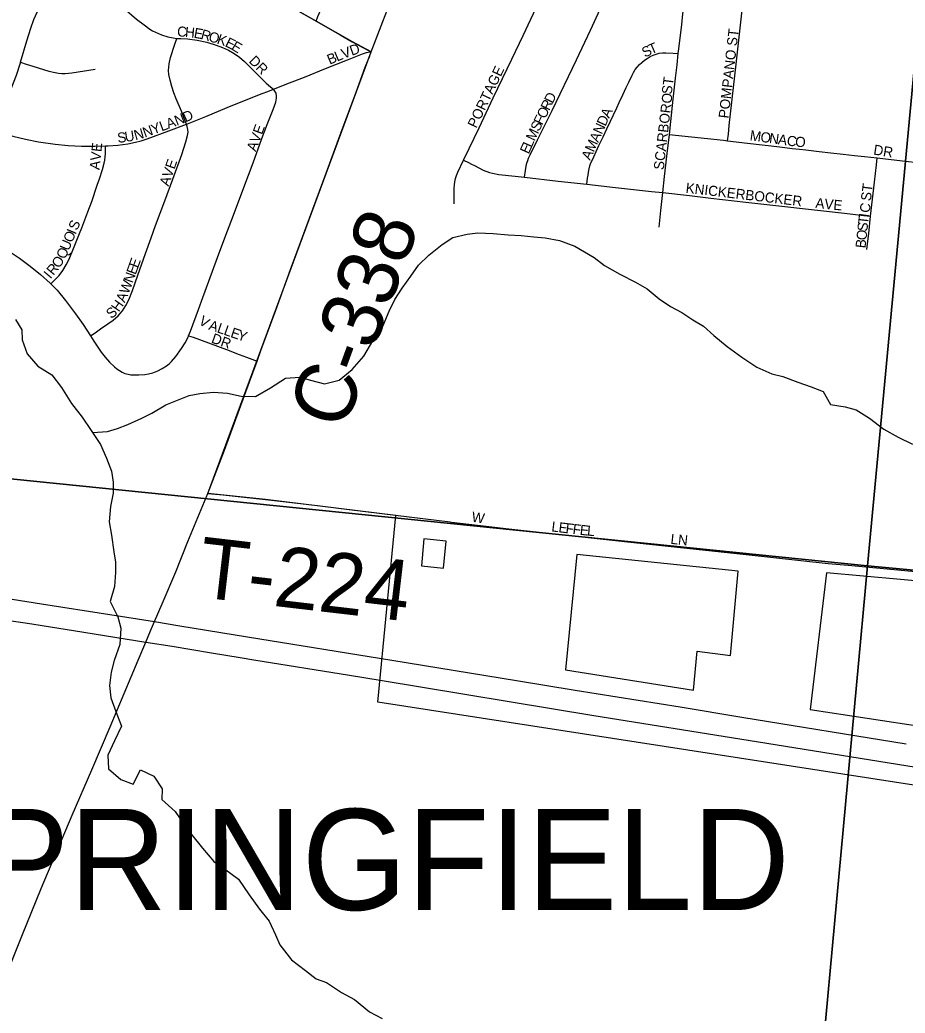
# Model space of a CAD drawing. Extents: x 1410790 to 1770854, y 566777 to 831614.
# Drawn here: x 1593644 to 1598025, y 690858 to 695774 of the extents above; entities that cross this region are included whole.
import ezdxf

# ---------------------------------------------------------------- set-up
doc = ezdxf.new("R2010")
doc.units = 0
for name, color, linetype in [('GM_X_City_Street', 7, 'Continuous'), ('GM_X_City_Street_Text', 7, 'Continuous'), ('GM_X_Corporation', 7, 'Continuous'), ('GM_X_Corporation_Text', 7, 'Continuous'), ('GM_X_County_Road', 7, 'Continuous'), ('GM_X_County_Road_Text', 7, 'Continuous'), ('GM_X_Interstate_Route', 7, 'Continuous'), ('GM_X_Minor_River', 7, 'Continuous'), ('GM_X_Section', 7, 'Continuous'), ('GM_X_Township_Road', 7, 'Continuous'), ('GM_X_Township_Road_Text', 7, 'Continuous'), ('GM_X_Township_Subdivision', 7, 'Continuous'), ('GM_X_Township_Subdivision_Text', 7, 'Continuous')]:
    doc.layers.add(name, color=color, linetype=linetype)

msp = doc.modelspace()

# ---------------------------------------------------------------- linework, layer by layer
at = {"layer": 'GM_X_City_Street'}
for points in [[(1595110.1, 695768.1), (1595119.1, 695790.4), (1595131.2, 695820.8), (1595178.5, 695942.9), (1595289.8, 696233.3), (1595315.8, 696299.8)], [(1595382.9, 695615.7), (1595440.5, 695766.1), (1595463.1, 695825), (1595487.8, 695889.4), (1595511.8, 695951.8), (1595534.4, 696010.7), (1595581.9, 696134.9), (1595587.8, 696150.3)], [(1595839.7, 695079.8), (1595867, 695137.8), (1595917.1, 695240.6), (1595985.7, 695388.6), (1596079, 695579.3), (1596134.3, 695696.7), (1596210.5, 695859), (1596315.6, 696080.8), (1596330.3, 696111)], [(1596141.3, 694995.2), (1596146.7, 695028.5), (1596151.8, 695059.3), (1596154.5, 695069.2), (1596157.5, 695078.2), (1596161.6, 695088.9), (1596169.7, 695106.9), (1596204.9, 695180.4), (1596277.9, 695326.3), (1596397.9, 695576.2), (1596468, 695723.4), (1596516.6, 695826.8), (1596588.4, 695979.6), (1596603.6, 696011.8)], [(1596902.6, 695607.3), (1596903.8, 695618.7), (1596909.9, 695669.7), (1596919.6, 695751.9), (1596925.7, 695803.7), (1596939.1, 695916), (1596942.6, 695945.7)], [(1597146.7, 695175.8), (1597150.3, 695208.8), (1597155, 695251.1), (1597188.7, 695554.2), (1597217.7, 695807.8), (1597226.5, 695885.8), (1597229.6, 695913.8)], [(1595367.5, 695576.3), (1595373.4, 695590.8), (1595378.1, 695603.2), (1595382.9, 695615.7)], [(1596449.7, 694960.7), (1596453.9, 694990.3), (1596456, 695005.1), (1596458, 695021.1), (1596461, 695036.9), (1596465.3, 695052.4), (1596469.8, 695066), (1596477.1, 695081.7), (1596503, 695138.2), (1596509.9, 695151.7), (1596530.9, 695195.3), (1596549.5, 695235.1), (1596567.1, 695272.7), (1596581.5, 695303.4), (1596597.8, 695338.1), (1596610.2, 695364.7), (1596628.4, 695403.5), (1596645.2, 695439.4), (1596657.4, 695465.4), (1596673.6, 695500), (1596680.7, 695514.3), (1596689.3, 695528), (1596699.4, 695540.8), (1596710.6, 695552.7), (1596722.6, 695563.9), (1596735.2, 695574.2), (1596748.5, 695583.7), (1596762.6, 695592.1), (1596777.4, 695599.1), (1596792.7, 695604.7), (1596808.6, 695608.7), (1596824.7, 695610.8), (1596841.1, 695611), (1596876.7, 695608.8), (1596902.6, 695607.3)], [(1596858.6, 695207.4), (1596865.8, 695271.8), (1596877.8, 695381.3), (1596889.2, 695484.9), (1596896.4, 695550.9), (1596902.6, 695607.3)], [(1596826.4, 694919), (1596835, 694998.2), (1596847.9, 695112.8), (1596858.6, 695207.4)], [(1596858.6, 695207.4), (1596889.5, 695204.1), (1597126.5, 695178.2), (1597146.7, 695175.8)], [(1597146.7, 695175.8), (1597244.9, 695164.1), (1597404.7, 695145.2), (1597465.7, 695138.3), (1597501.9, 695134.2), (1597534.5, 695130.5), (1597600, 695123.2), (1597657.2, 695116.7), (1597718.7, 695109.8), (1597775.2, 695103.4), (1597824.8, 695097.8), (1597887.7, 695090.9)], [(1595793.2, 694863), (1595793.2, 694895.4), (1595793.2, 694910.6), (1595792.9, 694925.7), (1595793.3, 694941), (1595794.4, 694956.9), (1595796.7, 694973.1), (1595800.4, 694989), (1595805.2, 695004.5), (1595811, 695019.8), (1595839.7, 695079.8)], [(1595839.7, 695079.8), (1595864.4, 695067.4), (1595878.7, 695060.3), (1595893, 695052.7), (1595936.9, 695030.9), (1595967.3, 695019.1), (1595983, 695014.7), (1596014.9, 695008.5), (1596095.9, 695000.4), (1596141.3, 694995.2)], [(1597854.7, 694802), (1597873.9, 694970.1), (1597883.7, 695055.9), (1597887.7, 695090.9)], [(1597887.7, 695090.9), (1598012.9, 695077.2), (1598102.8, 695067.3), (1598160.7, 695061), (1598188.8, 695057.9)], [(1596141.3, 694995.2), (1596307.8, 694976.6), (1596449.7, 694960.7)], [(1596449.7, 694960.7), (1596591.5, 694945), (1596770.7, 694925.1), (1596826.4, 694919)], [(1596808, 694748.2), (1596816.8, 694830.3), (1596826.4, 694919)], [(1596826.4, 694919), (1596958.3, 694904.3), (1597063.7, 694892.3), (1597237.5, 694872.5), (1597724.5, 694817), (1597820.4, 694805.9), (1597854.7, 694802)], [(1597835.6, 694637.4), (1597840.7, 694679.5), (1597845, 694717.1), (1597854.7, 694802)], [(1595780.3, 693288.6), (1595952.1, 693267.6), (1596049.7, 693256.7), (1596228.7, 693236.5), (1596456.6, 693212.3), (1596635.5, 693193), (1596944.7, 693159), (1597237.8, 693127.4), (1597644.9, 693084.2), (1597742.7, 693075.7), (1597970.9, 693054), (1598215.3, 693030.4), (1598464.3, 693001.6), (1598550.5, 692991.9), (1598670.4, 692978.3)]]:
    msp.add_lwpolyline(points, dxfattribs=at)
at = {"layer": 'GM_X_Corporation'}
msp.add_lwpolyline([(1598367.8, 691940.9), (1595414.7, 692397), (1595503.8, 693321.5), (1594859, 693400.6), (1594573.1, 693429.9), (1595382.9, 695615.7), (1595289.7, 695665.1), (1595110.1, 695768.1), (1594846.9, 695917.7)], dxfattribs=at)
for points in [[(1595753.4, 693194.7), (1595643.8, 693206.1), (1595631.3, 693071.7), (1595740.7, 693060.3)], [(1596399.9, 693127.7), (1596345, 692557.5), (1596977.3, 692456.4), (1596996.3, 692648.7), (1597161.2, 692628.6), (1597199.7, 693044.7)], [(1597636.9, 693037.6), (1597555.3, 692360.6), (1598119.6, 692275.5), (1598185.5, 692987.3)]]:
    msp.add_lwpolyline(points, close=True, dxfattribs=at)
at = {"layer": 'GM_X_County_Road'}
for points in [[(1594817.7, 694084.4), (1594836.8, 694137.1), (1594910.4, 694337.5), (1594983.2, 694538.3), (1595160.1, 695015.7), (1595238.9, 695231.7), (1595307.5, 695416.5), (1595352.8, 695539.9), (1595367.5, 695576.3)], [(1594573.1, 693429.9), (1594614.4, 693536.5), (1594655.6, 693643.7), (1594780.7, 693982.7), (1594817.7, 694084.4)], [(1594090.4, 692275.7), (1594229.6, 692605.1), (1594266.4, 692694.8), (1594289.5, 692750.9), (1594309.1, 692795.8), (1594347.7, 692883.8), (1594415.4, 693041.7), (1594475.3, 693191.9), (1594573.1, 693429.9)], [(1593504.9, 690861.3), (1593535.9, 690942.2), (1593614.2, 691140.3), (1593656.5, 691247), (1593749.7, 691474.5), (1593902.4, 691837), (1594000.3, 692062.5), (1594090.4, 692275.7)]]:
    msp.add_lwpolyline(points, dxfattribs=at)
at = {"layer": 'GM_X_Interstate_Route'}
for points in [[(1591241, 693062.9), (1591426.3, 693049.1), (1591646.2, 693033.2), (1592077.4, 692990.9), (1592343.8, 692964.5), (1592685.2, 692925.4), (1593005.4, 692884.2), (1593329.9, 692839.8), (1593702, 692784.8), (1593960.9, 692743.6), (1594266.4, 692694.8), (1594397.4, 692673.8), (1594592.6, 692641.4)], [(1593426.7, 692934.5), (1593750.7, 692884.2), (1594088.9, 692831.3), (1594309.1, 692795.8), (1594435.7, 692775.3), (1594770.6, 692720.3), (1595484.5, 692604.7), (1596101.1, 692504.7), (1596392.8, 692456.9), (1596911.3, 692373.5), (1597216.8, 692323), (1598030.7, 692191)], [(1594592.6, 692641.4), (1594734.6, 692617.8), (1594801, 692607.2)], [(1594801, 692607.2), (1595275.7, 692531.2), (1595426.6, 692506.2)], [(1595426.6, 692506.2), (1596485.1, 692331.4), (1597248, 692209.8), (1598356.7, 692030.2), (1598819.7, 691955.1), (1599147.3, 691901.2), (1599856.9, 691786.1)]]:
    msp.add_lwpolyline(points, dxfattribs=at)
at = {"layer": 'GM_X_Minor_River'}
for points in [[(1594003.3, 693731.9), (1594077, 693736.5), (1594127, 693752.2), (1594177.1, 693771.8), (1594247.3, 693803.3), (1594297.4, 693827), (1594365.6, 693868.5), (1594415.7, 693888.2), (1594481.8, 693915.7), (1594533.8, 693925.3), (1594601.8, 693930.8), (1594671.6, 693926.3), (1594739.4, 693911.8), (1594809.3, 693909.2), (1594883.6, 693952.7), (1594957.8, 694000.2), (1595029.8, 694005.7), (1595081.6, 693991.3), (1595151.4, 693972.8), (1595223.4, 693990.2), (1595287.7, 694043.8), (1595346.1, 694109.4), (1595390.6, 694185.2), (1595441.1, 694260.8), (1595471.6, 694332.7), (1595500, 694390.5), (1595536.4, 694446.3), (1595578.8, 694506), (1595617.1, 694559.8), (1595667.4, 694609.5), (1595733.8, 694663), (1595785.9, 694696.7), (1595858, 694714.1), (1595910, 694719.7), (1595985.8, 694717.2), (1596059.7, 694710.6), (1596125.6, 694706.1), (1596187.4, 694699.6), (1596243.3, 694695.2), (1596315.1, 694682.7), (1596390.8, 694654.1), (1596486.3, 694597.3), (1596537.9, 694558.9), (1596613.5, 694516.2), (1596691.1, 694475.6), (1596748.8, 694443.2), (1596808.3, 694392.7), (1596864, 694356.2), (1596919.7, 694325.8), (1596975.3, 694289.3), (1597027, 694258.9), (1597078.6, 694212.4), (1597144.1, 694157.9), (1597217.6, 694105.3), (1597291.1, 694054.7), (1597364.8, 694022.1), (1597420.6, 694009.6), (1597494.3, 693981), (1597560.1, 693958.5), (1597619.8, 693934), (1597655.3, 693869.7), (1597729.1, 693859.1), (1597782.9, 693844.7), (1597848.5, 693802.2), (1597920, 693747.6), (1597991.6, 693709), (1598061.3, 693674.4)], [(1593621.7, 694290.4), (1593653.3, 694240.1), (1593654.9, 694190.1), (1593680.4, 694121.8), (1593731.9, 694059.4), (1593801.5, 694016.8), (1593848.9, 693954.4), (1593898.3, 693876), (1593951.7, 693807.5), (1593997.1, 693741.1), (1594042.6, 693672.7), (1594072, 693604.4), (1594097.5, 693540.2), (1594105.1, 693486.1), (1594104.7, 693432), (1594092.2, 693366.1), (1594085.6, 693290.1), (1594097.1, 693223.9), (1594108.5, 693141.8), (1594116.1, 693089.7), (1594117.7, 693039.6), (1594111.2, 692969.6), (1594090.7, 692895.7), (1594128.1, 692819.3), (1594143.6, 692763.2), (1594139, 692683.1), (1594110.5, 692603.3), (1594096, 692545.3), (1594087.6, 692479.3), (1594093.1, 692419.2)], [(1594093.1, 692419.2), (1594118.6, 692351), (1594146, 692278.7), (1594111.5, 692204.9), (1594079, 692135.1), (1594082.5, 692067), (1594144, 692014.5), (1594203.7, 691992), (1594240.2, 692061.8), (1594305.9, 692031.3), (1594347.4, 691968.9), (1594347, 691914.9), (1594412.5, 691856.3), (1594452, 691798), (1594493.5, 691741.6), (1594546.9, 691675.2), (1594604.3, 691608.7), (1594656, 691572.3), (1594725.5, 691521.7), (1594778.9, 691443.2), (1594830.3, 691372.8), (1594877.8, 691312.4), (1594909.2, 691246.1), (1594930.8, 691195.9), (1594988.2, 691121.4), (1595057.7, 691068.8), (1595109.3, 691028.4), (1595161.1, 691010), (1595234.7, 690959.4), (1595300.3, 690924.9), (1595373.8, 690864.3), (1595437.4, 690831.8)]]:
    msp.add_lwpolyline(points, dxfattribs=at)
at = {"layer": 'GM_X_Section'}
for points in [[(1593108.3, 699057.6), (1598351.3, 698519.7), (1597838.4, 693072.3), (1592523.5, 693611.4)], [(1598351.3, 698519.7), (1603688.3, 697982.3), (1603189.9, 692572.7), (1597838.4, 693072.3)], [(1592523.5, 693611.4), (1597838.4, 693072.3), (1597349.3, 687756.6), (1592038.7, 688317.6)], [(1597838.4, 693072.3), (1603189.9, 692572.7), (1602694.7, 687247), (1597349.3, 687756.6)]]:
    msp.add_lwpolyline(points, close=True, dxfattribs=at)
at = {"layer": 'GM_X_Township_Road'}
msp.add_lwpolyline([(1594573.1, 693429.9), (1594650.4, 693423.5), (1594709.5, 693416.9), (1594859, 693400.6), (1594946, 693390.9), (1595116.4, 693370), (1595273.4, 693350.7), (1595435.3, 693330.9), (1595773.4, 693289.4), (1595780.3, 693288.6)], dxfattribs=at)
at = {"layer": 'GM_X_Township_Subdivision'}
for points in [[(1593646.8, 695564), (1593678, 695670), (1593698.5, 695732.5), (1593713.1, 695776.8), (1593720.4, 695794.2), (1593727.3, 695809.1), (1593735.5, 695823.3), (1593745, 695836.8), (1593755.8, 695849.2), (1593767.6, 695860.6), (1593780.2, 695871), (1593793.7, 695880.4), (1593807.9, 695888.7), (1593822.7, 695895.9), (1593838, 695901.9), (1593853.7, 695906.7), (1593869.8, 695910.2), (1593902.4, 695914), (1593935.2, 695916.8), (1593984.3, 695921.1), (1594016.9, 695925.3), (1594033, 695928.4), (1594048.9, 695932.6), (1594064.4, 695939.4)], [(1594064.4, 695939.4), (1594075, 695919.1), (1594087.2, 695900.1), (1594098.2, 695887.1), (1594111.1, 695873.4), (1594172.6, 695819.2), (1594196.2, 695799.1), (1594221.3, 695778.4), (1594258.4, 695749.1), (1594286.6, 695728.3), (1594300.5, 695719.8), (1594315, 695712.5), (1594345.3, 695700.6), (1594376.4, 695690.8), (1594402.2, 695684.7), (1594420.9, 695682.2)], [(1594846.9, 695917.7), (1594876.4, 695901.2), (1595075.2, 695788.2), (1595110.1, 695768.1)], [(1595110.1, 695768.1), (1595228.5, 695700), (1595287.6, 695666.2), (1595368.9, 695623.1), (1595382.9, 695615.7)], [(1594467.9, 695258.1), (1594460.8, 695278.4), (1594448.5, 695307.9), (1594442.9, 695323.1), (1594417.4, 695382.6), (1594405.6, 695412.9), (1594395.4, 695443.9), (1594386.9, 695475.5), (1594381.2, 695503.3), (1594380, 695524.1), (1594380.2, 695539.8), (1594382.6, 695556), (1594389.5, 695587.8), (1594393.6, 695603.4), (1594403.4, 695633.7), (1594409, 695649), (1594420.9, 695682.2)], [(1594420.9, 695682.2), (1594424.2, 695681.7), (1594440.2, 695681.4), (1594472.6, 695679.7), (1594520.9, 695673.4), (1594568.6, 695663), (1594615.5, 695649.3), (1594646.1, 695637.9), (1594675.6, 695624.4), (1594703.6, 695607.9), (1594730, 695588.8), (1594754.9, 695567.8), (1594778.6, 695545.4), (1594836.8, 695487.4), (1594862.8, 695461.4), (1594884, 695442.8), (1594898.4, 695431)], [(1594898.4, 695431), (1594978.8, 695462.5), (1595052.1, 695491.2), (1595156.9, 695533.3), (1595265.4, 695577), (1595339.5, 695605.8), (1595348.9, 695609.1), (1595359.6, 695612.2), (1595367.6, 695613.7), (1595382.9, 695615.7)], [(1593495.1, 695230.3), (1593514.9, 695262.9), (1593554.7, 695335), (1593576.8, 695379), (1593596.8, 695424), (1593626.2, 695500.2), (1593646, 695561.2), (1593646.8, 695564)], [(1593646.8, 695564), (1593674, 695555.4), (1593707.3, 695544.9), (1593786.7, 695520.9), (1593819, 695513.2), (1593835.3, 695510.6), (1593851.8, 695509.1), (1593868.3, 695509), (1593901.3, 695512.5), (1594016, 695530.5)], [(1594467.9, 695258.1), (1594472.6, 695259.9), (1594563.5, 695296.4), (1594669.2, 695340.2), (1594714.1, 695358.3), (1594842.3, 695409.6), (1594871.2, 695420.3), (1594898.4, 695431)], [(1594478.9, 694210.9), (1594488.6, 694233.7), (1594527.1, 694341.4), (1594549.6, 694399.6), (1594633.9, 694629.9), (1594672, 694730.7), (1594700.8, 694806.9), (1594752.3, 694944), (1594797.8, 695066), (1594841.1, 695186.9), (1594867.9, 695256.4), (1594897.2, 695330), (1594910.5, 695367.6), (1594914, 695386), (1594914, 695396.7), (1594911.4, 695411.9), (1594906.2, 695421.4), (1594898.4, 695431)], [(1593993.2, 694209.8), (1594016.3, 694225.9), (1594042.8, 694244.3), (1594079, 694269.4), (1594104.8, 694287.3), (1594129.5, 694308.6), (1594140.7, 694320.5), (1594151, 694333.2), (1594160.4, 694346.6), (1594168.7, 694360.6), (1594182.3, 694389.1), (1594200.6, 694434.1), (1594227.5, 694511), (1594265.4, 694618.6), (1594293, 694695.3), (1594315.5, 694756.5), (1594360.6, 694878.7), (1594400, 694985.8), (1594444.4, 695108.5), (1594465.2, 695170.3), (1594473.6, 695201.8), (1594475.9, 695217.9), (1594475.1, 695231), (1594472, 695246.3), (1594467.9, 695258.1)], [(1594067.8, 695150.6), (1594080, 695151), (1594129.1, 695154.8), (1594177.9, 695161.2), (1594215.1, 695168.2), (1594243.8, 695175.1), (1594273.3, 695184.7), (1594380.5, 695225.4), (1594467.9, 695258.1)], [(1593495.1, 695230.3), (1593545, 695216), (1593608, 695198.1), (1593672, 695183.2), (1593736.5, 695171), (1593817.8, 695159.6), (1593883.1, 695153.1), (1593948.7, 695149.4), (1594014.4, 695148.8), (1594067.8, 695150.6)], [(1593797.3, 694467.6), (1593819.4, 694490), (1593837.5, 694508.4), (1593856, 694533.4), (1593872.8, 694561.3), (1593887.4, 694590.4), (1593913, 694650.3), (1593939, 694716.8), (1593949.8, 694745.6), (1593979.9, 694824.4), (1593999.1, 694874.9), (1594026.8, 694955.7), (1594037, 694986.7), (1594052.8, 695032.9), (1594061.4, 695064.2), (1594064.5, 695080), (1594066.2, 695096), (1594066.7, 695111.1), (1594067.8, 695150.6)], [(1593162, 694877.1), (1593206.6, 694850.3), (1593262.7, 694818.3), (1593490.2, 694691), (1593587.6, 694631), (1593641.9, 694594.6), (1593694.4, 694555.7), (1593745.2, 694514.5), (1593794, 694471), (1593797.3, 694467.6)], [(1593797.3, 694467.6), (1593811.6, 694452.7), (1593827.8, 694435.6), (1593868.9, 694384.7), (1593918.4, 694319.7), (1593956.1, 694266.2), (1593993.2, 694209.8)], [(1593993.2, 694209.8), (1594010, 694184.3), (1594046.5, 694130.1), (1594066.3, 694104), (1594087.9, 694079.3), (1594111.5, 694057), (1594124, 694047.1), (1594136.5, 694038.3), (1594149.2, 694030.6), (1594163.5, 694024.6), (1594179.3, 694019.8), (1594192.8, 694017.2), (1594207, 694016.5), (1594232.2, 694016.5), (1594261.7, 694019.1), (1594281, 694021.6), (1594301.6, 694027.8), (1594325.9, 694037.3), (1594347.6, 694047.8), (1594369.7, 694061.8), (1594382.4, 694071.5), (1594394.1, 694082.6), (1594415.2, 694107.3), (1594443.9, 694147.2), (1594461, 694174.9), (1594475.8, 694203.7), (1594478.9, 694210.9)], [(1594478.9, 694210.9), (1594500.5, 694203), (1594666.8, 694142.1), (1594729.4, 694118.2), (1594765.6, 694104.3), (1594805.1, 694089.2), (1594817.7, 694084.4)]]:
    msp.add_lwpolyline(points, dxfattribs=at)

# ---------------------------------------------------------------- texts
at = {"layer": 'GM_X_City_Street_Text'}
for s, rotation, p in [('POMPANO ST', 83.5156, (1597151.2, 695284.6)), ('T', 23.3008, (1596768.1, 695602.4)), ('S', 27.6771, (1596737.9, 695586.5)), ('PORTAGE', 64.6117, (1595902.4, 695234.8)), ('ST', 82.8792, (1596869.6, 695403.5)), ('D', 63.9136, (1596280.7, 695356.9)), ('SCARBORO', 83.3347, (1596830, 695029.3)), ('R', 63.8966, (1596263.3, 695321.3)), ('F', 63.9176, (1596228.5, 695250.2)), ('O', 63.9042, (1596244, 695281.8)), ('A', 64.8966, (1596560, 695284.3)), ('S', 63.9236, (1596213, 695218.6)), ('N', 65.5958, (1596523.7, 695204.3)), ('D', 65.5759, (1596541.8, 695244.4)), ('M', 64.6283, (1596190.5, 695171)), ('A', 65.6078, (1596505.5, 695164.2)), ('M', 352.143, (1597254.3, 695178.5)), ('O', 352.1461, (1597306.6, 695171.3)), ('N', 352.1512, (1597350.2, 695165.2)), ('E', 66.0014, (1596161.9, 695107)), ('L', 65.9709, (1596176.2, 695139.1)), ('M', 65.59, (1596483.7, 695116.2)), ('A', 352.1403, (1597393.7, 695159.2)), ('C', 352.1437, (1597437.3, 695153.2)), ('O', 354.9697, (1597479.2, 695147.5)), ('A', 65.5958, (1596465.5, 695076.1)), ('DR', 351.0271, (1597866, 695108)), ('KNICKERBOCKER', 353.2904, (1596937.2, 694918.9)), ('ST', 82.8649, (1597855.2, 694875.5)), ('AVE', 354.0932, (1597579.5, 694844.1)), ('C', 80.8291, (1597848.5, 694816.4)), ('I', 82.1512, (1597845.5, 694794.9)), ('S', 83.8221, (1597837.8, 694725.3)), ('T', 83.5663, (1597841.6, 694760.2)), ('O', 83.8022, (1597833.1, 694681.5)), ('B', 83.8194, (1597828.8, 694642.2)), ('W', 351.2589, (1595877.2, 693290.8)), ('L', 353.2375, (1596272.8, 693242.5)), ('E', 353.2375, (1596307.8, 693238.3)), ('F', 353.2375, (1596342.8, 693234.2)), ('F', 353.2375, (1596377.7, 693230.1)), ('E', 353.5242, (1596413, 693225.9)), ('L', 355.4702, (1596449.8, 693221.7)), ('LN', 353.9934, (1596862.3, 693180.9))]:
    msp.add_text(s, height=50, rotation=rotation, dxfattribs=at).set_placement(p)
at = {"layer": 'GM_X_Corporation_Text'}
msp.add_text('SPRINGFIELD', height=500, rotation=0, dxfattribs=at).set_placement((1592995.9, 691368.4))
at = {"layer": 'GM_X_County_Road_Text'}
msp.add_text('C-338', height=300, rotation=69.9238, dxfattribs=at).set_placement((1595248.3, 693733.5))
at = {"layer": 'GM_X_Township_Road_Text'}
msp.add_text('T-224', height=300, rotation=353.3237, dxfattribs=at).set_placement((1594516.3, 692918.5))
at = {"layer": 'GM_X_Township_Subdivision_Text'}
for s, rotation, p in [('C', 354.8693, (1594420, 695693.3)), ('H', 354.8679, (1594459.5, 695689.8)), ('E', 350.2682, (1594502.3, 695686)), ('R', 344.9153, (1594535.7, 695680.3)), ('O', 343.7634, (1594573.7, 695670.1)), ('K', 342.0904, (1594615.6, 695657.9)), ('E', 333.5205, (1594655.6, 695645.1)), ('E', 328.9964, (1594686.2, 695629.9)), ('D', 19.4891, (1595286.3, 695596.1)), ('B', 22.7824, (1595176.9, 695551.8)), ('L', 22.7502, (1595213.4, 695567.2)), ('V', 20.7888, (1595245.4, 695580.6)), ('DR', 315, (1594773.6, 695567.4)), ('N', 20.9731, (1594419.8, 695249.4)), ('D', 23.9568, (1594463.5, 695266.3)), ('Y', 20.4734, (1594303.9, 695206.2)), ('L', 20.4569, (1594345.1, 695221.6)), ('A', 20.4661, (1594378.1, 695233.9)), ('AVE', 69.6803, (1594810.9, 695119.6)), ('S', 5.9118, (1594128.3, 695165.4)), ('U', 9.3655, (1594166.5, 695169.4)), ('N', 15.6429, (1594215.8, 695177.9)), ('N', 19.9591, (1594262.1, 695191)), ('AVE', 83.8878, (1594037.4, 695030.2)), ('AVE', 70.9762, (1594379.6, 694947.6)), ('S', 67.2803, (1593927.5, 694729.1)), ('O', 67.2844, (1593902.1, 694668.2)), ('I', 67.2893, (1593919.1, 694708.8)), ('U', 67.2699, (1593885, 694627.6)), ('Q', 66.3929, (1593867.1, 694586.5)), ('O', 56.4922, (1593838.3, 694541.5)), ('E', 70.2386, (1594228.3, 694542.8)), ('I', 49.8111, (1593794.9, 694489.3)), ('R', 50.0366, (1593809.2, 694506.2)), ('N', 70.2256, (1594201.5, 694468.3)), ('E', 70.2516, (1594216.4, 694509.7)), ('W', 69.0038, (1594180.6, 694413.8)), ('H', 55.6348, (1594132.7, 694325.6)), ('A', 67.1559, (1594162.8, 694371.6)), ('S', 40.7747, (1594096.7, 694292.1)), ('V', 327.471, (1594524.5, 694271.5)), ('A', 342.3053, (1594574.4, 694241.8)), ('L', 340.8608, (1594616, 694228.6)), ('L', 340.8649, (1594649.2, 694217)), ('E', 340.8649, (1594682.5, 694205.5)), ('Y', 340.8461, (1594715.7, 694193.9)), ('DR', 340.5566, (1594587.7, 694177.4))]:
    msp.add_text(s, height=50, rotation=rotation, dxfattribs=at).set_placement(p)

doc.saveas('drawing.dxf')
